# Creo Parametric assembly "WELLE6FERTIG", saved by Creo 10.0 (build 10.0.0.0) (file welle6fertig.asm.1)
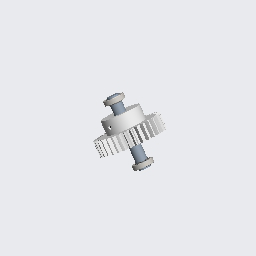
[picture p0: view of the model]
Units: millimeter Newton Second (mmNs); MM, TONNE, SECS

Created from: XX_INLBS_ASM_DESIGN_ABS.ASM

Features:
  1. datum plane "ASM_RIGHT"
  2. datum plane "ASM_TOP"
  3. datum plane "ASM_FRONT"
  4. coordinate system
  5. component "WELLE6NEW"
  6. component "ZAHNRAD6"
  7. component "KUGELLAGER"
  8. component "GEWINDE"
  9. component "KUGELLAGER"
  10. component "PRT0013"
  11. component "PRT0014"
  12. component "PRT0015"

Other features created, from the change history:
  component "PRT0002.PRT"
  component "PRT0003.PRT"
  component "PRT0004.PRT"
